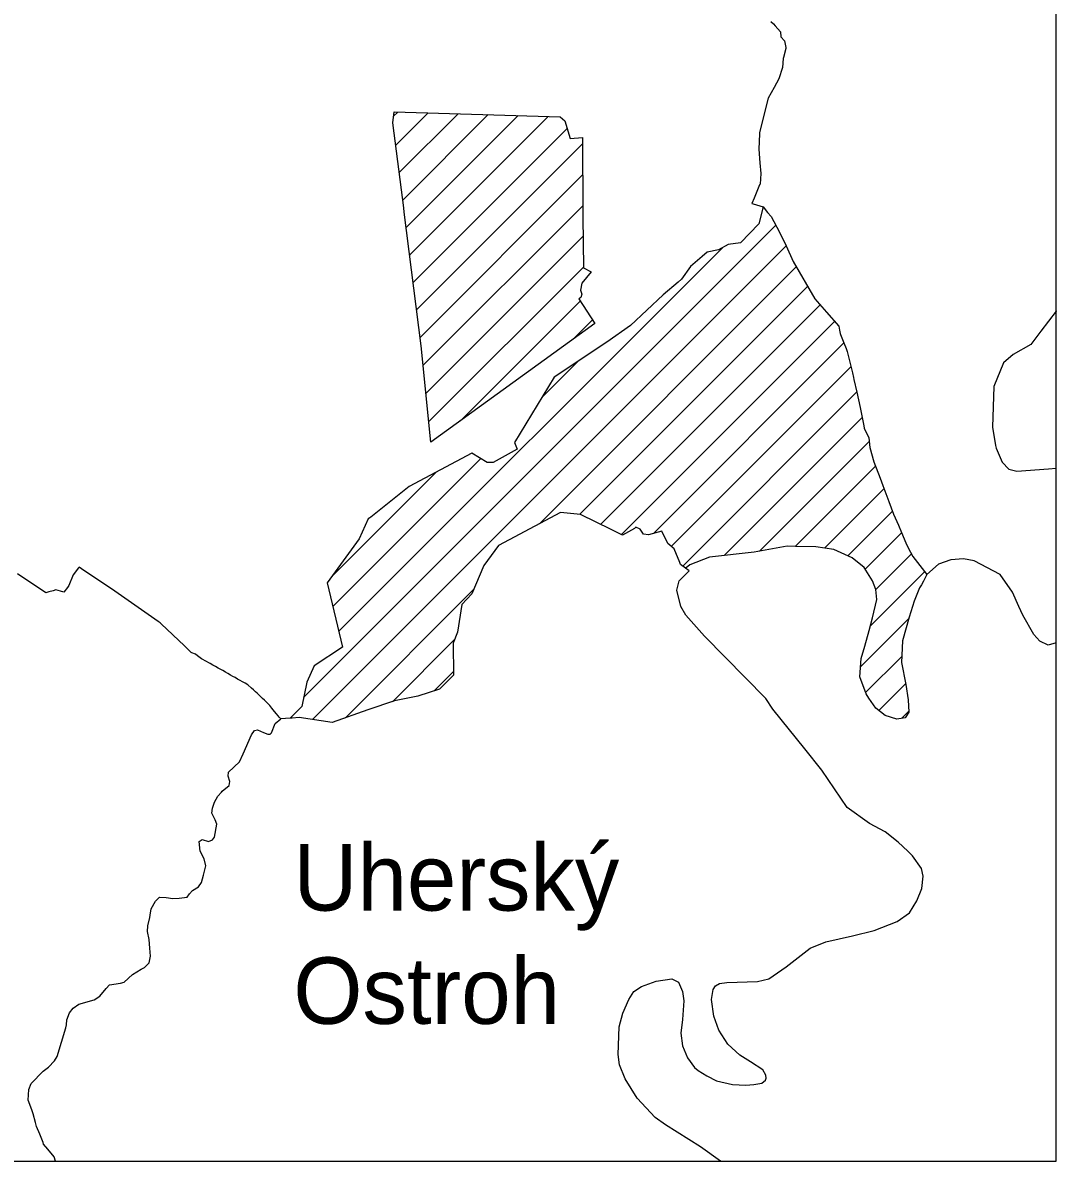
# Model space of a CAD drawing. Extents: x -552716 to -540720, y -1192685 to -1177912.
# Drawn here: x -546021 to -543896, y -1188366 to -1186025 of the extents above; entities that cross this region are included whole.
import ezdxf

# ---------------------------------------------------------------- set-up
doc = ezdxf.new("R2010")
doc.units = 0
for name, color, linetype in [('Default', 7, 'Continuous'), ('Vrstva 1', 7, 'Continuous'), ('Vrstva 2', 7, 'Continuous'), ('Vrstva 60', 7, 'Continuous')]:
    doc.layers.add(name, color=color, linetype=linetype)

msp = doc.modelspace()

# ---------------------------------------------------------------- linework, layer by layer
at = {"layer": 'Default'}
msp.add_lwpolyline([(-545257.7, -1186208.7), (-544916.4, -1186218.6), (-544907, -1186227.2), (-544895.5, -1186263.3), (-544870, -1186261.2), (-544869.9, -1186416.4), (-544869.8, -1186424.5), (-544868.6, -1186529.3), (-544852.4, -1186537.3), (-544871.5, -1186560.9), (-544874.7, -1186574.9), (-544871.4, -1186583.6), (-544873.7, -1186590.5), (-544877.8, -1186592.9), (-544845.1, -1186643.5), (-545182, -1186888), (-545202.1, -1186689.7), (-545236.9, -1186414.7), (-545238, -1186405.8), (-545260.1, -1186231.1)], close=True, dxfattribs=at)
msp.add_lwpolyline([(-544499.1, -1186404.2), (-544507.7, -1186438.8), (-544545.7, -1186477.7), (-544570.9, -1186481.2), (-544590.8, -1186492.2), (-544614, -1186497), (-544624.1, -1186505.8), (-544647.9, -1186526.7), (-544666.9, -1186552.8), (-544673.9, -1186558.8), (-544704.5, -1186585), (-544771.9, -1186647.9), (-544820.1, -1186682.1), (-544928.4, -1186754.4), (-545010.4, -1186888.4), (-545004.8, -1186902.1), (-545053.8, -1186929.4), (-545066.7, -1186929.4), (-545097.7, -1186910.1), (-545226.8, -1186979.2), (-545305.3, -1187041.9), (-545308, -1187043.5), (-545311.3, -1187045.5), (-545329.3, -1187086.9), (-545395.7, -1187176.8), (-545364.2, -1187309.6), (-545422.3, -1187348), (-545437.1, -1187381.6), (-545447.8, -1187431.3), (-545471.6, -1187455.5)], dxfattribs=at)
at = {"layer": 'Vrstva 1'}
for p, q in [((-544482.7, -1186022.8), (-544477.8, -1186027.9)), ((-544477.8, -1186027.9), (-544474.1, -1186032)), ((-544474.1, -1186032), (-544462.8, -1186043.9)), ((-544462.8, -1186043.9), (-544462.2, -1186054.4)), ((-544462.2, -1186054.4), (-544454.8, -1186062.6)), ((-544454.8, -1186062.6), (-544451.9, -1186076)), ((-544451.9, -1186076), (-544452.4, -1186078.1)), ((-544457.4, -1186098.6), (-544459.1, -1186117.7)), ((-544457.2, -1186097), (-544457.4, -1186098.6)), ((-544452.4, -1186078.1), (-544457.2, -1186097)), ((-544459.1, -1186117.7), (-544466.8, -1186141)), ((-544466.8, -1186141), (-544476.4, -1186158.3)), ((-544476.4, -1186158.3), (-544488.3, -1186180.1)), ((-544488.3, -1186180.1), (-544498.5, -1186220.9)), ((-544498.5, -1186220.9), (-544506.2, -1186251.8)), ((-544506.2, -1186253.5), (-544507.7, -1186285.6)), ((-544506.2, -1186251.8), (-544506.2, -1186253.5)), ((-544507.7, -1186285.6), (-544505.4, -1186313.2)), ((-544505.4, -1186313.2), (-544503.6, -1186335)), ((-544505.2, -1186357), (-544506.1, -1186358.9)), ((-544503.6, -1186335), (-544505.2, -1186357)), ((-544506.1, -1186358.9), (-544517.6, -1186385.8)), ((-544517.6, -1186385.8), (-544522.4, -1186396.8)), ((-544522.4, -1186396.8), (-544519.3, -1186397.8)), ((-544519.3, -1186397.8), (-544499.1, -1186404.2)), ((-544499.1, -1186404.2), (-544489.7, -1186415.7)), ((-544489.7, -1186415.7), (-544482.1, -1186424)), ((-544482.1, -1186424), (-544465.4, -1186456.3)), ((-544465.4, -1186456.3), (-544451.5, -1186484.3)), ((-544451.5, -1186484.3), (-544437.1, -1186516.5)), ((-544437.1, -1186516.5), (-544392.5, -1186593.2)), ((-544392.5, -1186593.2), (-544368.5, -1186620.8)), ((-544368.5, -1186620.8), (-544343.3, -1186649.3)), ((-544343.3, -1186649.3), (-544341.7, -1186657.6)), ((-544341.7, -1186657.6), (-544340.3, -1186664.5)), ((-544340.3, -1186664.5), (-544339.9, -1186666.5)), ((-544339.9, -1186666.5), (-544332.9, -1186683.5)), ((-544332.9, -1186683.5), (-544328, -1186695.1)), ((-544328, -1186695.1), (-544325.8, -1186701.2)), ((-544325.8, -1186701.2), (-544315.1, -1186745.4)), ((-544315.1, -1186745.4), (-544312.9, -1186754.8)), ((-544312.9, -1186754.8), (-544312, -1186758.6)), ((-544312, -1186758.6), (-544306.1, -1186785.1)), ((-544306.1, -1186785.1), (-544299.6, -1186816.4)), ((-544299.6, -1186816.4), (-544291.9, -1186853.9)), ((-544291.9, -1186853.9), (-544290.8, -1186859.2)), ((-544290.8, -1186859.2), (-544281.6, -1186879)), ((-544281.6, -1186879), (-544279.3, -1186898.8)), ((-544279.3, -1186898.8), (-544270.9, -1186928.2)), ((-544270.9, -1186928.2), (-544258.4, -1186962.1)), ((-544258.4, -1186962.1), (-544252.5, -1186976.8)), ((-544252.5, -1186976.8), (-544240.4, -1187009.5)), ((-544240.4, -1187009.5), (-544230.8, -1187035.9)), ((-544915.9, -1187032.4), (-545021.1, -1187088.5)), ((-544874.6, -1187036.2), (-544915.9, -1187032.4)), ((-544811.4, -1187067.1), (-544874.6, -1187036.2)), ((-544230.8, -1187035.9), (-544220.6, -1187058.8)), ((-544220.6, -1187058.8), (-544214.6, -1187073.4)), ((-544788.4, -1187078.8), (-544811.4, -1187067.1)), ((-544763.5, -1187065.1), (-544788.4, -1187078.8)), ((-544760.6, -1187062.7), (-544763.5, -1187065.1)), ((-544751.6, -1187066.4), (-544760.6, -1187062.7)), ((-544744.9, -1187076.7), (-544751.6, -1187066.4)), ((-544734.4, -1187078), (-544744.9, -1187076.7)), ((-544707.1, -1187070.6), (-544734.4, -1187078)), ((-544695.1, -1187096.1), (-544707.1, -1187070.6)), ((-544214.6, -1187073.4), (-544205.1, -1187094.6)), ((-545043.2, -1187100.6), (-545073.1, -1187141.5)), ((-545021.1, -1187088.5), (-545043.2, -1187100.6)), ((-544681.9, -1187107.1), (-544695.1, -1187096.1)), ((-544670.1, -1187135.3), (-544681.9, -1187107.1)), ((-544449.6, -1187101.9), (-544517.4, -1187114)), ((-544431.8, -1187102.1), (-544449.6, -1187101.9)), ((-544390.4, -1187103), (-544431.8, -1187102.1)), ((-544353.3, -1187108.4), (-544390.4, -1187103)), ((-544205.1, -1187094.6), (-544200.3, -1187105.2)), ((-544200.3, -1187105.2), (-544190.7, -1187122.9)), ((-544609.2, -1187124), (-544649.5, -1187140.3)), ((-544517.4, -1187114), (-544609.2, -1187124)), ((-544315.6, -1187125.5), (-544353.3, -1187108.4)), ((-544291, -1187145.4), (-544315.6, -1187125.5)), ((-544190.7, -1187122.9), (-544161.9, -1187160)), ((-545906.5, -1187146.1), (-545918.1, -1187160.7)), ((-545905.5, -1187144.8), (-545906.5, -1187146.1)), ((-545900.7, -1187148.5), (-545905.5, -1187144.8)), ((-545832, -1187194.2), (-545900.7, -1187148.5)), ((-545073.1, -1187141.5), (-545097.8, -1187199.4)), ((-544668.5, -1187139.1), (-544670.1, -1187135.3)), ((-544658.6, -1187147.1), (-544668.5, -1187139.1)), ((-544657.4, -1187146.2), (-544658.6, -1187147.1)), ((-544649.5, -1187140.3), (-544657.4, -1187146.2)), ((-544274, -1187172.9), (-544291, -1187145.4)), ((-545974.2, -1187197.8), (-546032.5, -1187158.3)), ((-545918.1, -1187160.7), (-545926.4, -1187182.7)), ((-544266.8, -1187191), (-544274, -1187172.9)), ((-544169.3, -1187173.5), (-544173.4, -1187181)), ((-544161.9, -1187160), (-544169.3, -1187173.5)), ((-545967.7, -1187195.8), (-545974.2, -1187197.8)), ((-545959.1, -1187193.2), (-545967.7, -1187195.8)), ((-545953.2, -1187191.4), (-545959.1, -1187193.2)), ((-545943.8, -1187194.4), (-545953.2, -1187191.4)), ((-545937.1, -1187196.5), (-545943.8, -1187194.4)), ((-545929.6, -1187186.8), (-545937.1, -1187196.5)), ((-545926.4, -1187182.7), (-545929.6, -1187186.8)), ((-545742.7, -1187256.5), (-545832, -1187194.2)), ((-545097.8, -1187199.4), (-545118.3, -1187221.7)), ((-544265.2, -1187211.6), (-544266.8, -1187191)), ((-544177, -1187187.5), (-544188, -1187214.8)), ((-544173.4, -1187181), (-544177, -1187187.5)), ((-545118.3, -1187221.7), (-545127.7, -1187278.2)), ((-544273.8, -1187248.9), (-544265.2, -1187211.6)), ((-544188, -1187214.8), (-544198.7, -1187247.8)), ((-544198.7, -1187247.8), (-544212.3, -1187296.4)), ((-545738.7, -1187259.6), (-545742.7, -1187256.5)), ((-545737.7, -1187260.4), (-545738.7, -1187259.6)), ((-545736.6, -1187261.2), (-545737.7, -1187260.4)), ((-545688.5, -1187306.7), (-545736.6, -1187261.2)), ((-544280.8, -1187275.1), (-544273.8, -1187248.9)), ((-545127.7, -1187278.2), (-545136.6, -1187301.3)), ((-544289.5, -1187307.4), (-544280.8, -1187275.1)), ((-545674.9, -1187320.4), (-545688.5, -1187306.7)), ((-545136.6, -1187301.3), (-545135.7, -1187366.9)), ((-544297.2, -1187332.4), (-544289.5, -1187307.4)), ((-544212.3, -1187296.4), (-544214.2, -1187341.1)), ((-545673.7, -1187320.9), (-545674.9, -1187320.4)), ((-545666.5, -1187323.9), (-545673.7, -1187320.9)), ((-545662.2, -1187327.3), (-545666.5, -1187323.9)), ((-545656.8, -1187331.1), (-545662.2, -1187327.3)), ((-545654.1, -1187333), (-545656.8, -1187331.1)), ((-545652.6, -1187333.8), (-545654.1, -1187333)), ((-545650.9, -1187334.8), (-545652.6, -1187333.8)), ((-545646.6, -1187337.2), (-545650.9, -1187334.8)), ((-545636.3, -1187342.9), (-545646.6, -1187337.2)), ((-544300.1, -1187370.5), (-544297.2, -1187332.4)), ((-544214.2, -1187341.1), (-544205.3, -1187386.1)), ((-545630.5, -1187346.3), (-545636.3, -1187342.9)), ((-545625.3, -1187349.1), (-545630.5, -1187346.3)), ((-545619.3, -1187352.5), (-545625.3, -1187349.1)), ((-545615.4, -1187354.7), (-545619.3, -1187352.5)), ((-545610.3, -1187357.6), (-545615.4, -1187354.7)), ((-545604.7, -1187360.8), (-545610.3, -1187357.6)), ((-545599.4, -1187363.7), (-545604.7, -1187360.8)), ((-545594.2, -1187366.6), (-545599.4, -1187363.7)), ((-545589.3, -1187369.4), (-545594.2, -1187366.6)), ((-545584.9, -1187371.9), (-545589.3, -1187369.4)), ((-545579.7, -1187374.8), (-545584.9, -1187371.9)), ((-545574.1, -1187377.9), (-545579.7, -1187374.8)), ((-545569.2, -1187380.7), (-545574.1, -1187377.9)), ((-545564, -1187383.6), (-545569.2, -1187380.7)), ((-545558.6, -1187386.6), (-545564, -1187383.6)), ((-545551.2, -1187393.5), (-545558.6, -1187386.6)), ((-545135.7, -1187366.9), (-545164.7, -1187395.9)), ((-544287.2, -1187405.4), (-544300.1, -1187370.5)), ((-544205.3, -1187386.1), (-544200.3, -1187417.6)), ((-545547.1, -1187397.3), (-545551.2, -1187393.5)), ((-545543, -1187401), (-545547.1, -1187397.3)), ((-545539.7, -1187404.1), (-545543, -1187401)), ((-545528.3, -1187414.6), (-545539.7, -1187404.1)), ((-545209.3, -1187410), (-545257.1, -1187420)), ((-545164.7, -1187395.9), (-545209.3, -1187410)), ((-544281.3, -1187414.1), (-544287.2, -1187405.4)), ((-545524.3, -1187418.2), (-545528.3, -1187414.6)), ((-545520, -1187422.2), (-545524.3, -1187418.2)), ((-545517.1, -1187424.9), (-545520, -1187422.2)), ((-545515.1, -1187427.3), (-545517.1, -1187424.9)), ((-545513.8, -1187428.9), (-545515.1, -1187427.3)), ((-545513.6, -1187429.1), (-545513.8, -1187428.9)), ((-545509.1, -1187434.6), (-545513.6, -1187429.1)), ((-545503.7, -1187441.3), (-545509.1, -1187434.6)), ((-545257.1, -1187420), (-545312, -1187438)), ((-544267, -1187434.8), (-544281.3, -1187414.1)), ((-544247.7, -1187449.6), (-544267, -1187434.8)), ((-544200.3, -1187417.6), (-544199, -1187443.2)), ((-545499.8, -1187446.1), (-545503.7, -1187441.3)), ((-545496.3, -1187450.4), (-545499.8, -1187446.1)), ((-545493.8, -1187453.4), (-545496.3, -1187450.4)), ((-545492.2, -1187455.4), (-545493.8, -1187453.4)), ((-545491, -1187456.9), (-545492.2, -1187455.4)), ((-545471.6, -1187455.5), (-545491, -1187456.9)), ((-545467.4, -1187455.2), (-545471.6, -1187455.5)), ((-545453.2, -1187454.2), (-545467.4, -1187455.2)), ((-545385, -1187464), (-545453.2, -1187454.2)), ((-545312, -1187438), (-545385, -1187464)), ((-544224, -1187457.4), (-544247.7, -1187449.6)), ((-544206.5, -1187454.9), (-544224, -1187457.4)), ((-544199, -1187443.2), (-544206.5, -1187454.9))]:
    msp.add_line(p, q, dxfattribs=at)
for points in [[(-543896.1, -1186618), (-543896.4, -1186618.2), (-543927.5, -1186659.3), (-543948.4, -1186686.9), (-543984.7, -1186707.2), (-544004.7, -1186724.5), (-544024.6, -1186773.3), (-544026.9, -1186856.7), (-544020.7, -1186894.4), (-544019.8, -1186900.3), (-544007.3, -1186929.1), (-543993.6, -1186943.2), (-543976.8, -1186947.1), (-543911.7, -1186942.5), (-543896.1, -1186941.3)], [(-543896.1, -1187300.5), (-543912.6, -1187304.9), (-543929.8, -1187296.9), (-543941.9, -1187283.6), (-543964.7, -1187243.5), (-543972.9, -1187225.4), (-543986, -1187196.4), (-544011.3, -1187159.9), (-544064.8, -1187131.7), (-544087.1, -1187127.8), (-544112.8, -1187129.7), (-544138, -1187138.8), (-544161.9, -1187160)], [(-544518, -1188208.6), (-544501.7, -1188205.6), (-544493.8, -1188199.8), (-544492.4, -1188195.4), (-544493, -1188189.5), (-544499.6, -1188178.1), (-544525, -1188162.3), (-544546.6, -1188148.4), (-544571.7, -1188125.7), (-544590, -1188096.7), (-544600.1, -1188068.3), (-544605, -1188034), (-544601.6, -1188013.2), (-544597.1, -1188005.5), (-544588.6, -1188000.9), (-544573.4, -1187999), (-544510.1, -1187997), (-544487, -1187991), (-544451.7, -1187966.4), (-544402.2, -1187928), (-544370, -1187915.4), (-544314.8, -1187902.9), (-544270.7, -1187892.1), (-544223, -1187873.6), (-544197.9, -1187855.5), (-544182.8, -1187831.2), (-544172.3, -1187805.8), (-544169.9, -1187780), (-544173.4, -1187764.5), (-544191.7, -1187738.5), (-544201.6, -1187729.1), (-544220.9, -1187710.6), (-544248.2, -1187689.3), (-544280.4, -1187671.8), (-544325.9, -1187638.8), (-544378.4, -1187562.5), (-544413, -1187518.3), (-544478.8, -1187436.7), (-544493.3, -1187415.1), (-544619.5, -1187286.7), (-544657.9, -1187243.8), (-544667.9, -1187225.4), (-544676, -1187192.2), (-544671.4, -1187173.1), (-544651.3, -1187152.5), (-544658.6, -1187147.1)], [(-545993.2, -1188295.1), (-545995.2, -1188286.4), (-545999.7, -1188269.2), (-546002.5, -1188260.7), (-546010.3, -1188240.5), (-546008.8, -1188218.9), (-546003.9, -1188206.4), (-545979.4, -1188181.4), (-545968.8, -1188172.8), (-545956.4, -1188159.7), (-545950.8, -1188151.3), (-545932.7, -1188091.9), (-545931.8, -1188086.2), (-545931.1, -1188075.4), (-545925.1, -1188061.2), (-545917.9, -1188051.7), (-545905.8, -1188043.1), (-545874.8, -1188034.8), (-545863.2, -1188027.2), (-545849.9, -1188011.1), (-545842.8, -1188003.8), (-545820.5, -1188000), (-545813.2, -1187998), (-545795.7, -1187982.5), (-545778.2, -1187971.7), (-545770.8, -1187968), (-545761.6, -1187958.2), (-545758.9, -1187944.5), (-545759.8, -1187928), (-545761.8, -1187910.5), (-545765, -1187894), (-545764.4, -1187882.2), (-545760.3, -1187865.4), (-545759.1, -1187860.5), (-545757.5, -1187847.3), (-545748.2, -1187831.6), (-545740.3, -1187823.5), (-545726.2, -1187824), (-545712.9, -1187826), (-545699.9, -1187825.6), (-545683.6, -1187823.6), (-545678.5, -1187816.7), (-545672.2, -1187809.4), (-545660, -1187802.1), (-545653.7, -1187793.1), (-545650, -1187778.3), (-545645, -1187759), (-545648.6, -1187744.4), (-545656.4, -1187728.6), (-545658.5, -1187708.7), (-545652.4, -1187705), (-545639.6, -1187709), (-545631.4, -1187705.8), (-545626.9, -1187699.9), (-545622.5, -1187673.5), (-545625.8, -1187664.1), (-545632.3, -1187650.5), (-545631.3, -1187640.1), (-545627.2, -1187628.1), (-545620, -1187615.6), (-545612.8, -1187607.5), (-545611.4, -1187605.2), (-545597.2, -1187594), (-545595.9, -1187585.4), (-545599.3, -1187574.3), (-545598.1, -1187566.2), (-545575.6, -1187544.9), (-545568.5, -1187528.9), (-545551.3, -1187489.3), (-545544.6, -1187480.5), (-545538.6, -1187479.4), (-545526.6, -1187484.6), (-545517.6, -1187488.2), (-545512.6, -1187488.2), (-545509.8, -1187485.5), (-545502.2, -1187466.1), (-545491, -1187456.9)], [(-544585.9, -1188366.4), (-544586.5, -1188365.9), (-544627.9, -1188336.9), (-544699.7, -1188291.5), (-544720.6, -1188276.5), (-544757.6, -1188236.8), (-544782.8, -1188197.1), (-544794.1, -1188168.2), (-544797.2, -1188146.9), (-544794.7, -1188089.8), (-544787.3, -1188061.9), (-544775.3, -1188034), (-544764.5, -1188017.2), (-544748.8, -1188007.2), (-544719.1, -1187996.2), (-544686.8, -1187991.1), (-544672.9, -1187998.5), (-544664.9, -1188017.7), (-544661.9, -1188036.4), (-544664.7, -1188075), (-544667.8, -1188102.7), (-544664.7, -1188129.1), (-544654.4, -1188153.8), (-544640.1, -1188173.5), (-544632.8, -1188179.8), (-544614.8, -1188190.9), (-544594.7, -1188201), (-544561.8, -1188208.3), (-544534.6, -1188210.2), (-544518, -1188208.6)], [(-545954.3, -1188366.4), (-545957, -1188357), (-545969.6, -1188341.5), (-545978.8, -1188331.1), (-545979.8, -1188327.6), (-545986.4, -1188311), (-545993.2, -1188295.1)]]:
    msp.add_lwpolyline(points, dxfattribs=at)
at = {"layer": 'Vrstva 2'}
for p, q in [((-545258.7, -1186217.7), (-545249.9, -1186208.9)), ((-545254.3, -1186276.9), (-545188, -1186210.7)), ((-545247.1, -1186333.4), (-545126.2, -1186212.5)), ((-545240, -1186389.9), (-545064.3, -1186214.3)), ((-545232.8, -1186446.4), (-545002.5, -1186216.1)), ((-545225.7, -1186502.9), (-544940.6, -1186217.9)), ((-545218.5, -1186559.4), (-544902, -1186242.9)), ((-545211.4, -1186615.9), (-544870, -1186274.5)), ((-545204.3, -1186672.4), (-544870, -1186338.1)), ((-545198, -1186729.8), (-544869.9, -1186401.7)), ((-544499.3, -1186404.7), (-544498.9, -1186404.4)), ((-545443.9, -1187413), (-544472.8, -1186441.9)), ((-545192.2, -1186787.6), (-544869.3, -1186464.8)), ((-545425.4, -1187458.2), (-544451.5, -1186484.3)), ((-545371.9, -1187277.3), (-544581.7, -1186487.2)), ((-545186.3, -1186845.4), (-544868.6, -1186527.7)), ((-544959, -1187055.4), (-544430.8, -1186527.2)), ((-544876, -1187036), (-544407.4, -1186567.5)), ((-545121, -1186843.7), (-544874.9, -1186597.6)), ((-544832.9, -1187056.6), (-544381.8, -1186605.5)), ((-544888.9, -1186675.3), (-544849.8, -1186636.2)), ((-544790.4, -1187077.8), (-544352.1, -1186639.4)), ((-544724.3, -1187075.3), (-544332.8, -1186683.8)), ((-544953.4, -1186795.3), (-544880.7, -1186722.5)), ((-544687.7, -1187102.3), (-544318.2, -1186732.8)), ((-544664.3, -1187142.5), (-544306.2, -1186784.5)), ((-544578.8, -1187120.7), (-544295.3, -1186837.2)), ((-544506.5, -1187112.1), (-544280.7, -1186886.3)), ((-545384, -1187225.9), (-545079.6, -1186921.4)), ((-544432.9, -1187102), (-544267.7, -1186936.9)), ((-545387.4, -1187165.7), (-545171.1, -1186949.3)), ((-544372.8, -1187105.6), (-544250.2, -1186983)), ((-544324.9, -1187121.3), (-544233.1, -1187029.5)), ((-544288.8, -1187148.9), (-544214.2, -1187074.3)), ((-544267, -1187190.7), (-544193.7, -1187117.4)), ((-544278.3, -1187265.7), (-544166.6, -1187154)), ((-545357.9, -1187454.3), (-545094, -1187190.4)), ((-544298.5, -1187349.5), (-544199.4, -1187250.4)), ((-545261.3, -1187421.4), (-545133.7, -1187293.8)), ((-544288.2, -1187402.8), (-544213.7, -1187328.3)), ((-545175.7, -1187399.4), (-545135.8, -1187359.5)), ((-544261.1, -1187439.4), (-544205.7, -1187384)), ((-544214, -1187455.9), (-544199.1, -1187441))]:
    msp.add_line(p, q, dxfattribs=at)
at = {"layer": 'Vrstva 60'}
msp.add_lwpolyline([(-543896.1, -1181161.6), (-549696, -1181161.6), (-549696, -1188366.4), (-543896.1, -1188366.4)], close=True, dxfattribs=at)

# ---------------------------------------------------------------- texts
at = {"layer": 'Vrstva 1'}
for s, p in [('Uherský', (-545465, -1187851)), ('Ostroh', (-545465, -1188083.9))]:
    msp.add_text(s, height=136.69, dxfattribs=at).set_placement(p)

doc.saveas('drawing.dxf')
